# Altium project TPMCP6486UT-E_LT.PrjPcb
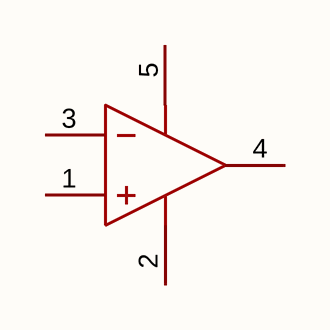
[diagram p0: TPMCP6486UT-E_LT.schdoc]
1 sheet, 1 parts. Net scope: global (net labels, ports and power ports of the same name join across sheets).

## Sheet TPMCP6486UT-E_LT.schdoc
size 127 x 101 mm

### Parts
U?  tpmcp6486ut-e/lt  [SOT-353-5_L2.0-W1.6-P0.65-LS2.1-BL]  (value not drawn)

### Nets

Not connected (* = marked no-connect by the designer): U? 1(IN+) 2(VSS) 3(IN-) 4(OUT) 5(VDD)

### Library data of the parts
U? = tpmcp6486ut-e/lt: Manufacturer: TECH PUBLIC(台舟); AddInBom: yes; ModelId: 09e153e3f5c7488aac8a155ea9f165d5; ModelTransform: 78.74,82.677,0,0,0,0,0,0,0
